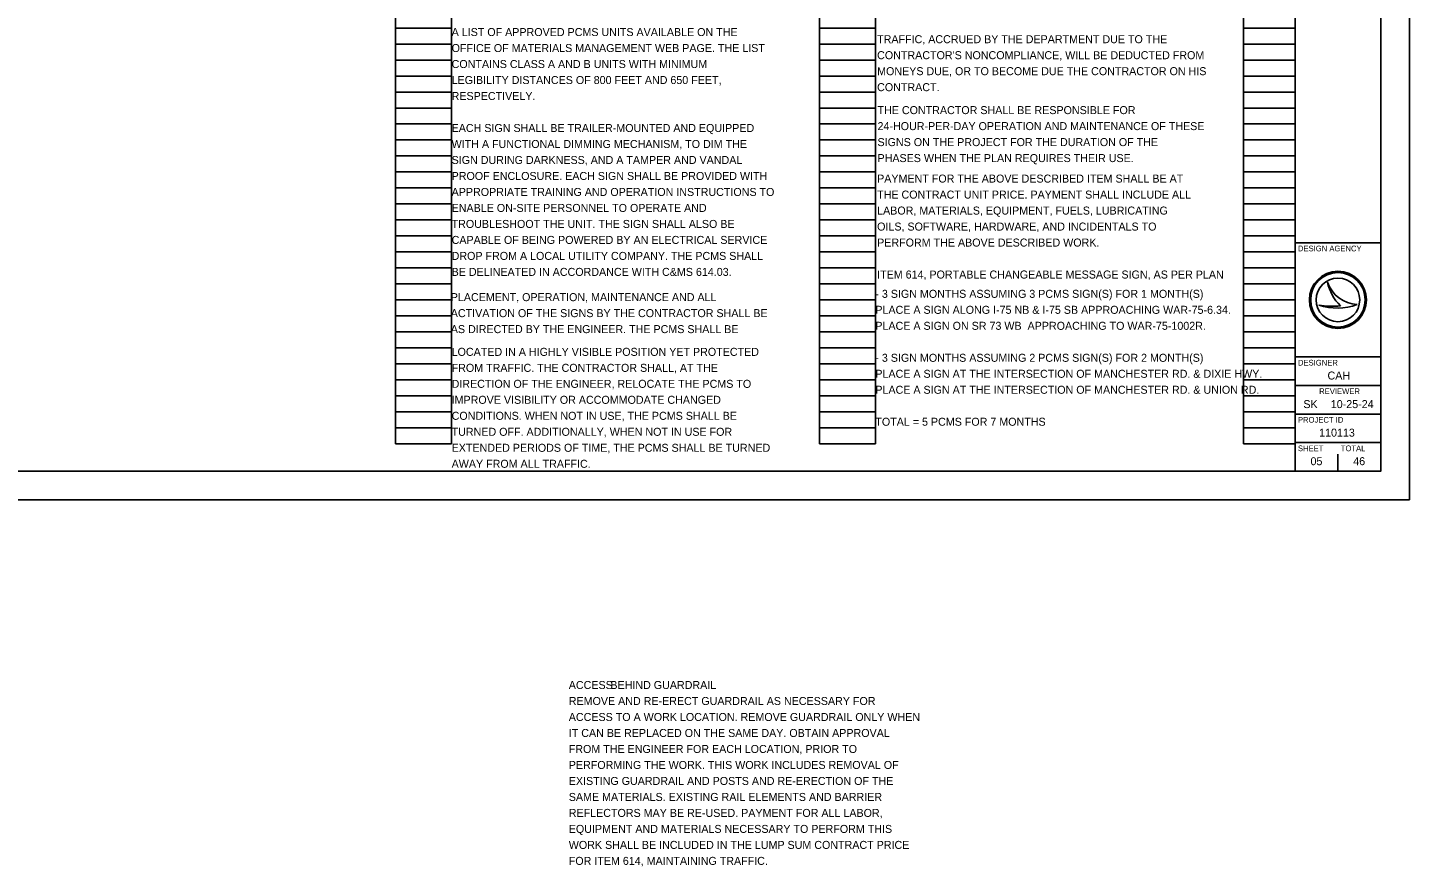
# Model space of a CAD drawing. Extents: x -7 to 34, y -38.9 to 22.
# Drawn here: x 9.82 to 34, y -6.42 to 8.27 of the extents above; entities that cross this region are included whole.
import ezdxf

# ---------------------------------------------------------------- set-up
doc = ezdxf.new("R2010")
doc.units = 0
for name, color, linetype in [('SH_Border', 7, 'Continuous'), ('SH_Cut_Line', 7, 'Continuous'), ('SH_Data', 7, 'Continuous'), ('SH_Text', 7, 'Continuous')]:
    doc.layers.add(name, color=color, linetype=linetype)

msp = doc.modelspace()

# ---------------------------------------------------------------- linework, layer by layer
at = {"layer": 'SH_Border'}
for p, q in [((16.26, 0.98), (16.26, 21.14)), ((17.24, 0.98), (17.24, 21.14)), ((23.68, 0.98), (23.68, 21.14)), ((24.66, 0.98), (24.66, 21.14)), ((31.1, 0.98), (31.1, 21.14)), ((32, 0.98), (32, 21.14)), ((16.26, 8.26), (17.24, 8.26)), ((23.68, 8.26), (24.66, 8.26)), ((31.1, 8.26), (32, 8.26)), ((16.26, 7.98), (17.24, 7.98)), ((23.68, 7.98), (24.66, 7.98)), ((31.1, 7.98), (32, 7.98)), ((16.26, 7.7), (17.24, 7.7)), ((23.68, 7.7), (24.66, 7.7)), ((31.1, 7.7), (32, 7.7)), ((16.26, 7.42), (17.24, 7.42)), ((23.68, 7.42), (24.66, 7.42)), ((31.1, 7.42), (32, 7.42)), ((16.26, 7.14), (17.24, 7.14)), ((23.68, 7.14), (24.66, 7.14)), ((31.1, 7.14), (32, 7.14)), ((16.26, 6.86), (17.24, 6.86)), ((23.68, 6.86), (24.66, 6.86)), ((31.1, 6.86), (32, 6.86)), ((16.26, 6.58), (17.24, 6.58)), ((23.68, 6.58), (24.66, 6.58)), ((31.1, 6.58), (32, 6.58)), ((16.26, 6.3), (17.24, 6.3)), ((23.68, 6.3), (24.66, 6.3)), ((31.1, 6.3), (32, 6.3)), ((16.26, 6.02), (17.24, 6.02)), ((23.68, 6.02), (24.66, 6.02)), ((31.1, 6.02), (32, 6.02)), ((16.26, 5.74), (17.24, 5.74)), ((23.68, 5.74), (24.66, 5.74)), ((31.1, 5.74), (32, 5.74)), ((16.26, 5.46), (17.24, 5.46)), ((23.68, 5.46), (24.66, 5.46)), ((31.1, 5.46), (32, 5.46)), ((16.26, 5.18), (17.24, 5.18)), ((23.68, 5.18), (24.66, 5.18)), ((31.1, 5.18), (32, 5.18)), ((16.26, 4.9), (17.24, 4.9)), ((23.68, 4.9), (24.66, 4.9)), ((31.1, 4.9), (32, 4.9)), ((16.26, 4.62), (17.24, 4.62)), ((23.68, 4.62), (24.66, 4.62)), ((31.1, 4.62), (32, 4.62)), ((16.26, 4.34), (17.24, 4.34)), ((23.68, 4.34), (24.66, 4.34)), ((31.1, 4.34), (32, 4.34)), ((16.26, 4.06), (17.24, 4.06)), ((23.68, 4.06), (24.66, 4.06)), ((31.1, 4.06), (32, 4.06)), ((16.26, 3.78), (17.24, 3.78)), ((23.68, 3.78), (24.66, 3.78)), ((31.1, 3.78), (32, 3.78)), ((32.567, 3.81), (32.567, 3.81)), ((16.26, 3.5), (17.24, 3.5)), ((23.68, 3.5), (24.66, 3.5)), ((31.1, 3.5), (32, 3.5)), ((32.417, 3.41), (32.417, 3.41)), ((32.75, 3.5), (32.75, 3.5)), ((33.087, 3.419), (33.087, 3.419)), ((16.26, 3.22), (17.24, 3.22)), ((23.68, 3.22), (24.66, 3.22)), ((31.1, 3.22), (32, 3.22)), ((16.26, 2.94), (17.24, 2.94)), ((23.68, 2.94), (24.66, 2.94)), ((31.1, 2.94), (32, 2.94)), ((16.26, 2.66), (17.24, 2.66)), ((23.68, 2.66), (24.66, 2.66)), ((31.1, 2.66), (32, 2.66)), ((16.26, 2.38), (17.24, 2.38)), ((23.68, 2.38), (24.66, 2.38)), ((31.1, 2.38), (32, 2.38)), ((16.26, 2.1), (17.24, 2.1)), ((23.68, 2.1), (24.66, 2.1)), ((31.1, 2.1), (32, 2.1)), ((16.26, 1.82), (17.24, 1.82)), ((23.68, 1.82), (24.66, 1.82)), ((31.1, 1.82), (32, 1.82)), ((16.26, 1.54), (17.24, 1.54)), ((23.68, 1.54), (24.66, 1.54)), ((31.1, 1.54), (32, 1.54)), ((16.26, 1.26), (17.24, 1.26)), ((23.68, 1.26), (24.66, 1.26)), ((31.1, 1.26), (32, 1.26)), ((16.26, 0.98), (17.24, 0.98)), ((23.68, 0.98), (24.66, 0.98)), ((31.1, 0.98), (32, 0.98)), ((32.75, 0.5), (32.75, 0.8)), ((32.375, 0.675), (32.375, 0.675))]:
    msp.add_line(p, q, dxfattribs=at)
for radius in [0.5, 0.477, 0.477, 0.382]:
    msp.add_circle((32.75, 3.5), radius, dxfattribs=at)
for centre, radius, start, end in [((33.116, 3.998), 0.58, 198.9257, 198.9319), ((33.347, 3.97), 0.796, 191.6379, 191.6421), ((33.116, 3.998), 0.58, 198.9319, 267.1657), ((33.347, 3.97), 0.796, 191.6421, 226.0947), ((32.739, 4.37), 1.013, 251.4576, 290.0832), ((32.648, 4.654), 1.266, 259.4964, 259.4995), ((32.739, 4.37), 1.013, 251.4527, 251.4576), ((32.648, 4.654), 1.266, 259.4995, 276.6672)]:
    msp.add_arc(centre, radius, start, end, dxfattribs=at)
at = {"layer": 'SH_Cut_Line'}
for p, q in [((32, 0.5), (32, 21.5)), ((32, 4.5), (33.5, 4.5)), ((32, 2.5), (33.5, 2.5)), ((32, 2), (33.5, 2)), ((32, 1.5), (33.5, 1.5)), ((32, 1), (33.5, 1))]:
    msp.add_line(p, q, dxfattribs=at)
msp.add_lwpolyline([(1.5, 21.5), (33.5, 21.5), (33.5, 0.5), (1.5, 0.5)], close=True, dxfattribs=at)
at = {"layer": 'SH_Text'}
msp.add_lwpolyline([(0, 0), (34, 0), (34, 22), (0, 22)], close=True, dxfattribs=at)

# ---------------------------------------------------------------- texts
at = {"layer": 'SH_Border'}
for s, height, p in [('DESIGN AGENCY', 0.1, (32.05, 4.35)), ('DESIGNER', 0.1, (32.05, 2.35)), ('CAH', 0.14, (32.568, 2.105)), ('REVIEWER', 0.1, (32.422, 1.85)), ('SK', 0.14, (32.145, 1.605)), ('10-25-24', 0.14, (32.625, 1.605)), ('PROJECT ID', 0.1, (32.05, 1.35)), ('110113', 0.14, (32.421, 1.105)), ('SHEET', 0.1, (32.05, 0.85)), ('05', 0.14, (32.27, 0.605)), ('TOTAL', 0.1, (32.8, 0.85)), ('46', 0.14, (33.018, 0.605))]:
    msp.add_text(s, height=height, dxfattribs=at).set_placement(p)
at = {"layer": 'SH_Data'}
for s, p in [('A LIST OF APPROVED PCMS UNITS AVAILABLE ON THE', (17.24, 8.12)), ('OFFICE OF MATERIALS MANAGEMENT WEB PAGE. THE LIST', (17.24, 7.84)), ('TRAFFIC, ACCRUED BY THE DEPARTMENT DUE TO THE', (24.686, 7.995)), ("CONTRACTOR'S NONCOMPLIANCE, WILL BE DEDUCTED FROM", (24.686, 7.715)), ('CONTAINS CLASS A AND B UNITS WITH MINIMUM', (17.24, 7.56)), ('MONEYS DUE, OR TO BECOME DUE THE CONTRACTOR ON HIS', (24.686, 7.435)), ('LEGIBILITY DISTANCES OF 800 FEET AND 650 FEET,', (17.24, 7.28)), ('CONTRACT.', (24.686, 7.155)), ('RESPECTIVELY.', (17.24, 7)), ('THE CONTRACTOR SHALL BE RESPONSIBLE FOR', (24.693, 6.753)), ('EACH SIGN SHALL BE TRAILER-MOUNTED AND EQUIPPED', (17.24, 6.44)), ('24-HOUR-PER-DAY OPERATION AND MAINTENANCE OF THESE', (24.693, 6.473)), ('WITH A FUNCTIONAL DIMMING MECHANISM, TO DIM THE', (17.24, 6.16)), ('SIGNS ON THE PROJECT FOR THE DURATION OF THE', (24.693, 6.193)), ('PHASES WHEN THE PLAN REQUIRES THEIR USE.', (24.693, 5.913)), ('SIGN DURING DARKNESS, AND A TAMPER AND VANDAL', (17.24, 5.88)), ('PROOF ENCLOSURE. EACH SIGN SHALL BE PROVIDED WITH', (17.24, 5.6)), ('PAYMENT FOR THE ABOVE DESCRIBED ITEM SHALL BE AT', (24.686, 5.554)), ('APPROPRIATE TRAINING AND OPERATION INSTRUCTIONS TO', (17.24, 5.32)), ('THE CONTRACT UNIT PRICE. PAYMENT SHALL INCLUDE ALL', (24.686, 5.274)), ('ENABLE ON-SITE PERSONNEL TO OPERATE AND', (17.24, 5.04)), ('LABOR, MATERIALS, EQUIPMENT, FUELS, LUBRICATING', (24.686, 4.994)), ('TROUBLESHOOT THE UNIT. THE SIGN SHALL ALSO BE', (17.24, 4.76)), ('OILS, SOFTWARE, HARDWARE, AND INCIDENTALS TO', (24.686, 4.714)), ('CAPABLE OF BEING POWERED BY AN ELECTRICAL SERVICE', (17.24, 4.48)), ('PERFORM THE ABOVE DESCRIBED WORK.', (24.686, 4.434)), ('DROP FROM A LOCAL UTILITY COMPANY. THE PCMS SHALL', (17.24, 4.2)), ('BE DELINEATED IN ACCORDANCE WITH C&MS 614.03.', (17.24, 3.92)), ('ITEM 614, PORTABLE CHANGEABLE MESSAGE SIGN, AS PER PLAN', (24.686, 3.874)), ('- 3 SIGN MONTHS ASSUMING 3 PCMS SIGN(S) FOR 1 MONTH(S)', (24.655, 3.536)), ('PLACEMENT, OPERATION, MAINTENANCE AND ALL', (17.225, 3.478)), ('PLACE A SIGN ALONG I-75 NB & I-75 SB APPROACHING WAR-75-6.34.', (24.655, 3.256)), ('ACTIVATION OF THE SIGNS BY THE CONTRACTOR SHALL BE', (17.225, 3.198)), ('AS DIRECTED BY THE ENGINEER. THE PCMS SHALL BE', (17.225, 2.918)), ('PLACE A SIGN ON SR 73 WB  APPROACHING TO WAR-75-1002R.', (24.655, 2.976)), ('LOCATED IN A HIGHLY VISIBLE POSITION YET PROTECTED', (17.24, 2.52)), ('- 3 SIGN MONTHS ASSUMING 2 PCMS SIGN(S) FOR 2 MONTH(S)', (24.655, 2.416)), ('FROM TRAFFIC. THE CONTRACTOR SHALL, AT THE', (17.24, 2.24)), ('PLACE A SIGN AT THE INTERSECTION OF MANCHESTER RD. & DIXIE HWY.', (24.655, 2.136)), ('DIRECTION OF THE ENGINEER, RELOCATE THE PCMS TO', (17.24, 1.96)), ('PLACE A SIGN AT THE INTERSECTION OF MANCHESTER RD. & UNION RD.', (24.655, 1.856)), ('IMPROVE VISIBILITY OR ACCOMMODATE CHANGED', (17.24, 1.68)), ('CONDITIONS. WHEN NOT IN USE, THE PCMS SHALL BE', (17.24, 1.4)), ('TURNED OFF. ADDITIONALLY, WHEN NOT IN USE FOR', (17.24, 1.12)), ('TOTAL = 5 PCMS FOR 7 MONTHS', (24.655, 1.296)), ('EXTENDED PERIODS OF TIME, THE PCMS SHALL BE TURNED', (17.24, 0.84)), ('AWAY FROM ALL TRAFFIC.', (17.24, 0.56)), ('ACCESS', (19.29, -3.314)), ('BEHIND GUARDRAIL', (20.018, -3.314)), ('REMOVE AND RE-ERECT GUARDRAIL AS NECESSARY FOR', (19.29, -3.594)), ('ACCESS TO A WORK LOCATION. REMOVE GUARDRAIL ONLY WHEN', (19.29, -3.874)), ('IT CAN BE REPLACED ON THE SAME DAY. OBTAIN APPROVAL ', (19.29, -4.154)), ('FROM THE ENGINEER FOR EACH LOCATION, PRIOR TO', (19.29, -4.434)), ('PERFORMING THE WORK. THIS WORK INCLUDES REMOVAL OF', (19.29, -4.714)), ('EXISTING GUARDRAIL AND POSTS AND RE-ERECTION OF THE', (19.29, -4.994)), ('SAME MATERIALS. EXISTING RAIL ELEMENTS AND BARRIER', (19.29, -5.274)), ('REFLECTORS MAY BE RE-USED. PAYMENT FOR ALL LABOR,', (19.29, -5.554)), ('EQUIPMENT AND MATERIALS NECESSARY TO PERFORM THIS', (19.29, -5.834)), ('WORK SHALL BE INCLUDED IN THE LUMP SUM CONTRACT PRICE', (19.29, -6.114)), ('FOR ITEM 614, MAINTAINING TRAFFIC.', (19.29, -6.394))]:
    msp.add_text(s, height=0.14, dxfattribs=at).set_placement(p)

doc.saveas('drawing.dxf')
